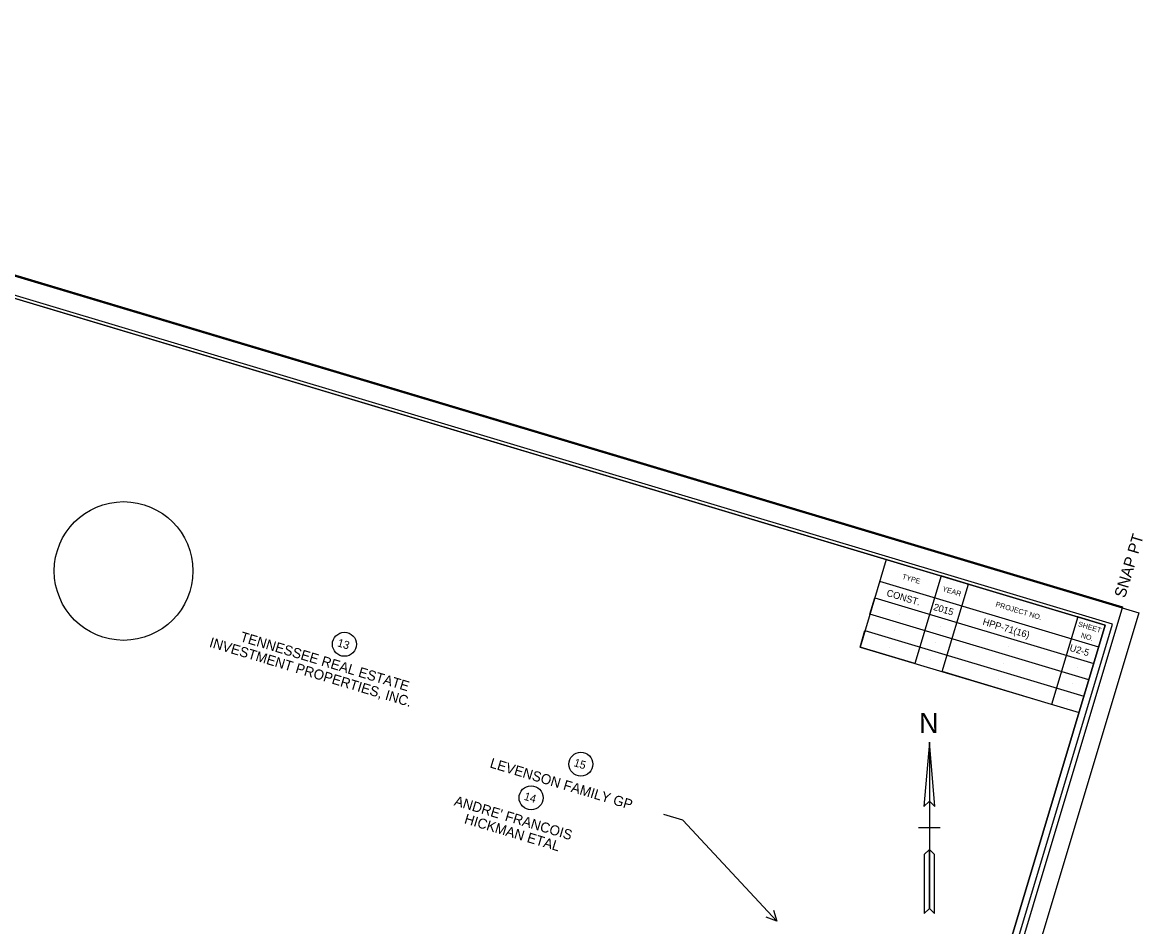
# Model space of a CAD drawing. Extents: x 2627582 to 2629622, y 568931 to 570612.
# Drawn here: x 2628642 to 2629622, y 569779 to 570571 of the extents above; entities that cross this region are included whole.
import ezdxf

# ---------------------------------------------------------------- set-up
doc = ezdxf.new("R2010")
doc.units = 0
for name, color, linetype in [('DESIGN - CENTERLINE - Proposed Text', 7, 'Continuous'), ('DESIGN - SCRATCH - User 1', 7, 'Continuous'), ('DESIGN - SHEET - Corner Text', 7, 'Continuous'), ('DESIGN - SHEET - Light Grid', 7, 'Continuous'), ('DESIGN - SHEET - Linework', 7, 'Continuous'), ('DESIGN - SHEET - Plot Shape', 7, 'Continuous'), ('SURVEY - PROJECT INFORMATION and NOTES', 7, 'Continuous'), ('SURVEY - PROPERTY - Owners', 7, 'Continuous'), ('SURVEY - PROPERTY - Tract Numbers', 7, 'Continuous')]:
    doc.layers.add(name, color=color, linetype=linetype)

msp = doc.modelspace()

# ---------------------------------------------------------------- linework, layer by layer
at = {"layer": 'DESIGN - CENTERLINE - Proposed Text'}
for p, q in [((2629435.34, 569865.62), (2629425.89, 569865.62)), ((2629444.79, 569865.62), (2629435.34, 569865.62))]:
    msp.add_line(p, q, dxfattribs=at)
msp.add_lwpolyline([(2629435.34, 569940.62), (2629430.44, 569884.32), (2629435.34, 569889.22), (2629440.24, 569884.32), (2629435.34, 569940.62), (2629435.34, 569795.17), (2629439.89, 569790.62), (2629439.89, 569842.37), (2629435.34, 569846.92), (2629430.79, 569842.37), (2629430.79, 569790.62), (2629435.34, 569795.17)], dxfattribs=at)
for points in [[(2629435.34, 569889.22), (2629440.24, 569884.32), (2629435.34, 569940.62)], [(2629430.79, 569790.62), (2629435.34, 569795.17), (2629435.34, 569846.92), (2629430.79, 569842.37)]]:
    msp.add_lwpolyline(points, close=True, dxfattribs=at)
at = {"layer": 'DESIGN - SCRATCH - User 1'}
for p, q in [((2629413.7, 570067.08), (2629413.7, 570067.08)), ((2629409.4, 570052.72), (2629409.4, 570052.72)), ((2629449.14, 570056.46), (2629449.14, 570056.46)), ((2629444.84, 570042.09), (2629444.84, 570042.09)), ((2629405.09, 570038.35), (2629405.09, 570038.35)), ((2629509.01, 570038.51), (2629509.01, 570038.51)), ((2629400.78, 570023.98), (2629400.78, 570023.98)), ((2629440.53, 570027.72), (2629440.53, 570027.72)), ((2629504.71, 570024.15), (2629504.71, 570024.15)), ((2629568.88, 570020.57), (2629568.88, 570020.57)), ((2629436.22, 570013.36), (2629436.22, 570013.36)), ((2629500.4, 570009.78), (2629500.4, 570009.78)), ((2629564.57, 570006.2), (2629564.57, 570006.2)), ((2629496.09, 569995.41), (2629496.09, 569995.41)), ((2629560.27, 569991.83), (2629560.27, 569991.83)), ((2629555.96, 569977.46), (2629555.96, 569977.46))]:
    msp.add_line(p, q, dxfattribs=at)
at = {"layer": 'DESIGN - SHEET - Light Grid'}
msp.add_lwpolyline([(2627697.64, 569511.43), (2629292.52, 569033.35), (2629595.46, 570043.92), (2628000.57, 570522.01)], close=True, dxfattribs=at)
at = {"layer": 'DESIGN - SHEET - Linework'}
for p, q in [((2627894.35, 570570.76), (2629618.55, 570053.91)), ((2629618.55, 570053.91), (2629306.31, 569012.3))]:
    msp.add_line(p, q, dxfattribs=at)
for points in [[(2628081.32, 570495.19), (2627779.83, 569489.41), (2629287.73, 569037.39), (2629589.23, 570043.18), (2628081.32, 570495.19)], [(2629397.65, 570100.61), (2629374.68, 570023.97), (2629566.26, 569966.55), (2629589.23, 570043.18), (2629565.28, 570050.36), (2629542.31, 569973.72), (2629446.52, 570002.44), (2629469.49, 570079.07), (2629445.55, 570086.25), (2629422.58, 570009.62), (2629374.68, 570023.97), (2629378.99, 570038.34), (2629570.57, 569980.91), (2629574.87, 569995.28), (2629383.29, 570052.71), (2629387.6, 570067.08), (2629579.18, 570009.65), (2629583.49, 570024.02), (2629391.91, 570081.45)]]:
    msp.add_lwpolyline(points, dxfattribs=at)
at = {"layer": 'DESIGN - SHEET - Plot Shape'}
for points in [[(2627975.91, 570547.35), (2629604.32, 570059.22), (2629291.51, 569015.7), (2627663.1, 569503.83)], [(2627999.85, 570519.61), (2629589.23, 570043.18), (2629287.73, 569037.39), (2627698.36, 569513.83)]]:
    msp.add_lwpolyline(points, close=True, dxfattribs=at)
at = {"layer": 'SURVEY - PROJECT INFORMATION and NOTES'}
msp.add_circle((2628730.27, 570090.56), 60.7, dxfattribs=at)
at = {"layer": 'SURVEY - PROPERTY - Tract Numbers'}
for points in [[(2629219.73, 569872.44), (2629202.96, 569877.47)], [(2629301.81, 569784.18), (2629219.73, 569872.44)], [(2629299.05, 569793.57), (2629301.81, 569784.18), (2629292.65, 569787.61)]]:
    msp.add_lwpolyline(points, dxfattribs=at)
for centre in [(2628923.49, 570026.4), (2629130.39, 569921.48), (2629086.82, 569892.04)]:
    msp.add_circle(centre, 10.5, dxfattribs=at)

# ---------------------------------------------------------------- texts
at = {"layer": 'DESIGN - CENTERLINE - Proposed Text'}
msp.add_text('N', height=17.72, dxfattribs=at).set_placement((2629426.29, 569948.67))
at = {"layer": 'DESIGN - SHEET - Corner Text'}
for s, height, rotation, p in [('  SNAP PT', 10, 73.31329, (2629604.32, 570059.22)), ('TYPE', 4.5, 343.31329, (2629411.1, 570083.84)), ('CONST.', 6, 343.31329, (2629397.37, 570068.85)), ('YEAR', 4.5, 343.31329, (2629446.3, 570073.08)), ('2015', 6, 343.31329, (2629438.33, 570056.57)), ('PROJECT NO.', 4.5, 343.31329, (2629492.87, 570059.54)), ('HPP-71(16)', 6, 343.31329, (2629481.46, 570043.64)), ('SHEET', 4.5, 343.31329, (2629565.09, 570042.22)), ('NO.', 4.5, 343.31329, (2629567.52, 570032.41)), ('U2-5', 6, 343.31329, (2629557.5, 570020.85))]:
    msp.add_text(s, height=height, rotation=rotation, dxfattribs=at).set_placement(p)
at = {"layer": 'SURVEY - PROPERTY - Owners'}
for s, p in [('INVESTMENT PROPERTIES, INC.', (2628804.66, 570024.29)), ('TENNESSEE REAL ESTATE', (2628831.6, 570029.26)), ('LEVENSON FAMILY GP', (2629050.15, 569918.71)), ("ANDRE' FRANCOIS", (2629018.88, 569885.58)), ('HICKMAN ETAL', (2629027.76, 569869.87))]:
    msp.add_text(s, height=8.75, rotation=343.31329, dxfattribs=at).set_placement(p)
at = {"layer": 'SURVEY - PROPERTY - Tract Numbers'}
for s, p in [('13', (2628916.73, 570024.77)), ('15', (2629123.63, 569919.86)), ('14', (2629080.06, 569890.42))]:
    msp.add_text(s, height=7, rotation=343.31329, dxfattribs=at).set_placement(p)

doc.saveas('drawing.dxf')
